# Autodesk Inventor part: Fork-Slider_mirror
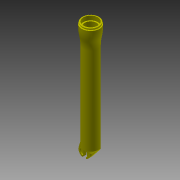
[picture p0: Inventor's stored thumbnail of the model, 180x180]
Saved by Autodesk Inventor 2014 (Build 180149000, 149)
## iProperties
Shininess: 64.0
Length Units: 11272
Angle Units: 11279
Time Units: 11290
Mass Units: 11286
Length Display Precision: 3
Angle Display Precision: 2
Compacted: True
Part Number: Fork-Slider_mirror
Document SubType Name: Modeling
Created: 2003-10
Designer: Autodesk, Inc.
Material: Generic
Manufacturer: Standard
Standards Organization: Custom
Mass: 115.052 g
Surface Area: 625.893 cm^2
Volume: 115.052 cm^3
Density: 1 g/cm^3
Appearance: Yellow (Flat)
Density: 0.0
Volumn: 0.0
Area: 0.0
PropertySet Name: Model Information
Control State: 0
Master: False
Checked Out: False
Author: Autodesk, Inc.
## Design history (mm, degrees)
derived "Fork-Slider.ipt"
  workplane "Work Plane3"
  node "WorkPlane4"
  workplane "Work Plane8"
  node "WorkPlane5"
  node "WorkPlane1"
  node "WorkPlane2"
  node "WorkPlane3"
  node "WorkAxis1"
body "Solid1"
tag "TaggingFeature2"
workplane "Work Plane10"
workplane "Work Plane11"
workplane "Work Plane5"
workplane "Work Plane6"
feature "DerivedBody::Fork-Slider.ipt"
